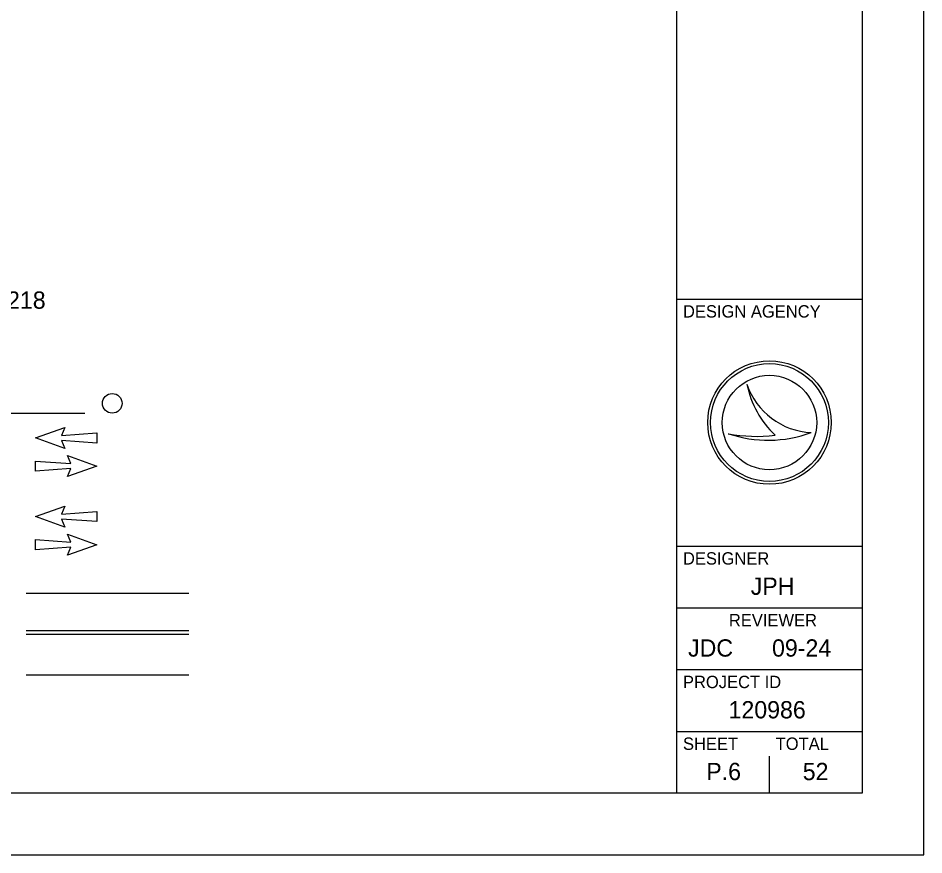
# Model space of a CAD drawing. Extents: x 396.2 to 468.4, y 232.6 to 279.1.
# Drawn here: x 422.87 to 430.2, y 257.12 to 263.89 of the extents above; entities that cross this region are included whole.
import ezdxf

# ---------------------------------------------------------------- set-up
doc = ezdxf.new("R2010")
doc.units = 0
for name, color, linetype in [('SH_Border', 7, 'Continuous'), ('SH_Cut_Line', 7, 'Continuous'), ('SH_Data', 7, 'Continuous'), ('TX_P_1', 7, 'Continuous')]:
    doc.layers.add(name, color=color, linetype=linetype)

msp = doc.modelspace()

# ---------------------------------------------------------------- linework, layer by layer
at = {"layer": 'SH_Border'}
for p, q in [((428.2027, 257.6206), (428.2027, 278.6206)), ((428.2027, 261.6206), (429.7027, 261.6206)), ((428.2027, 259.6206), (429.7027, 259.6206)), ((428.2027, 259.1206), (429.7027, 259.1206)), ((428.2027, 258.6206), (429.7027, 258.6206)), ((428.2027, 258.1206), (429.7027, 258.1206))]:
    msp.add_line(p, q, dxfattribs=at)
msp.add_lwpolyline([(397.7027, 278.6206), (429.7027, 278.6206), (429.7027, 257.6206), (397.7027, 257.6206)], close=True, dxfattribs=at)
at = {"layer": 'SH_Cut_Line'}
msp.add_lwpolyline([(396.2027, 257.1206), (430.2027, 257.1206), (430.2027, 279.1206), (396.2027, 279.1206)], close=True, dxfattribs=at)
at = {"layer": 'SH_Data'}
for p, q in [((428.7701, 260.9301), (428.7701, 260.9301)), ((428.9527, 260.6206), (428.9527, 260.6206)), ((428.6199, 260.5301), (428.6199, 260.5301)), ((429.29, 260.5391), (429.29, 260.5391)), ((428.9527, 257.6206), (428.9527, 257.9206)), ((428.5777, 257.7956), (428.5777, 257.7956))]:
    msp.add_line(p, q, dxfattribs=at)
for radius in [0.5, 0.4768, 0.4768, 0.3822]:
    msp.add_circle((428.9527, 260.6206), radius, dxfattribs=at)
for centre, radius, start, end in [((429.3186, 261.1182), 0.5798, 198.92567, 198.93195), ((429.5494, 261.0906), 0.7956, 191.63793, 191.64215), ((429.3186, 261.1182), 0.5798, 198.93195, 267.16574), ((429.5494, 261.0906), 0.7956, 191.64215, 226.09467), ((428.9421, 261.4906), 1.0131, 251.45764, 290.08324), ((428.8507, 261.7749), 1.2661, 259.49639, 259.49952), ((428.9421, 261.4906), 1.0131, 251.45274, 251.45764), ((428.8507, 261.7749), 1.2661, 259.49952, 276.66723)]:
    msp.add_arc(centre, radius, start, end, dxfattribs=at)
at = {"layer": 'TX_P_1'}
for p, q in [((423.4103, 260.6931), (418.3926, 260.6931)), ((423.0107, 260.4959), (423.2487, 260.5811)), ((423.2487, 260.5811), (423.2234, 260.5163)), ((423.2486, 260.4104), (423.0107, 260.4959)), ((423.2234, 260.5163), (423.5092, 260.5365)), ((423.5092, 260.5365), (423.5092, 260.4549)), ((423.5092, 260.4549), (423.2235, 260.4753)), ((423.2235, 260.4753), (423.2486, 260.4104)), ((423.2967, 260.2888), (423.2712, 260.3536)), ((423.2712, 260.3536), (423.5094, 260.2682)), ((423.0108, 260.2276), (423.0106, 260.3088)), ((423.0106, 260.3088), (423.2967, 260.2888)), ((423.2967, 260.2476), (423.0108, 260.2276)), ((423.5094, 260.2682), (423.2715, 260.183)), ((423.2715, 260.183), (423.2967, 260.2476)), ((423.0107, 259.8596), (423.2487, 259.9448)), ((423.2487, 259.9448), (423.2234, 259.88)), ((423.2486, 259.7742), (423.0107, 259.8596)), ((423.2234, 259.88), (423.5092, 259.9002)), ((423.5092, 259.8186), (423.2235, 259.8391)), ((423.2235, 259.8391), (423.2486, 259.7742)), ((423.5092, 259.9002), (423.5092, 259.8186)), ((423.2967, 259.6525), (423.2712, 259.7173)), ((423.2712, 259.7173), (423.5094, 259.6319)), ((423.0108, 259.5913), (423.0106, 259.6725)), ((423.0106, 259.6725), (423.2967, 259.6525)), ((423.2967, 259.6114), (423.0108, 259.5913)), ((423.5094, 259.6319), (423.2715, 259.5467)), ((423.2715, 259.5467), (423.2967, 259.6114)), ((424.2532, 259.2376), (422.9359, 259.2376)), ((424.2532, 258.9338), (422.9359, 258.9338)), ((424.2532, 258.9039), (422.9359, 258.9039)), ((424.2532, 258.5752), (422.9359, 258.5752))]:
    msp.add_line(p, q, dxfattribs=at)
msp.add_circle((423.6329, 260.776), 0.0797, dxfattribs=at)

# ---------------------------------------------------------------- texts
at = {"layer": 'SH_Data'}
for s, height, p in [('DESIGN AGENCY', 0.1, (428.2527, 261.4706)), ('DESIGNER', 0.1, (428.2527, 259.4706)), ('JPH', 0.14, (428.8011, 259.2256)), ('REVIEWER', 0.1, (428.6245, 258.9706)), ('JDC', 0.14, (428.2939, 258.7256)), ('09-24', 0.14, (428.9736, 258.7256)), ('PROJECT ID', 0.1, (428.2527, 258.4706)), ('120986', 0.14, (428.6218, 258.2256)), ('SHEET', 0.1, (428.2527, 257.9706)), ('TOTAL', 0.1, (429.0027, 257.9706)), ('P.6', 0.14, (428.4413, 257.7256)), ('52', 0.14, (429.2221, 257.7256))]:
    msp.add_text(s, height=height, dxfattribs=at).set_placement(p)
at = {"layer": 'TX_P_1'}
msp.add_text('STATE DETOUR: SR 218 TO SR 553 TO SR 7 BACK TO SR 218', height=0.14, dxfattribs=at).set_placement((417.6008, 261.5419))

doc.saveas('drawing.dxf')
